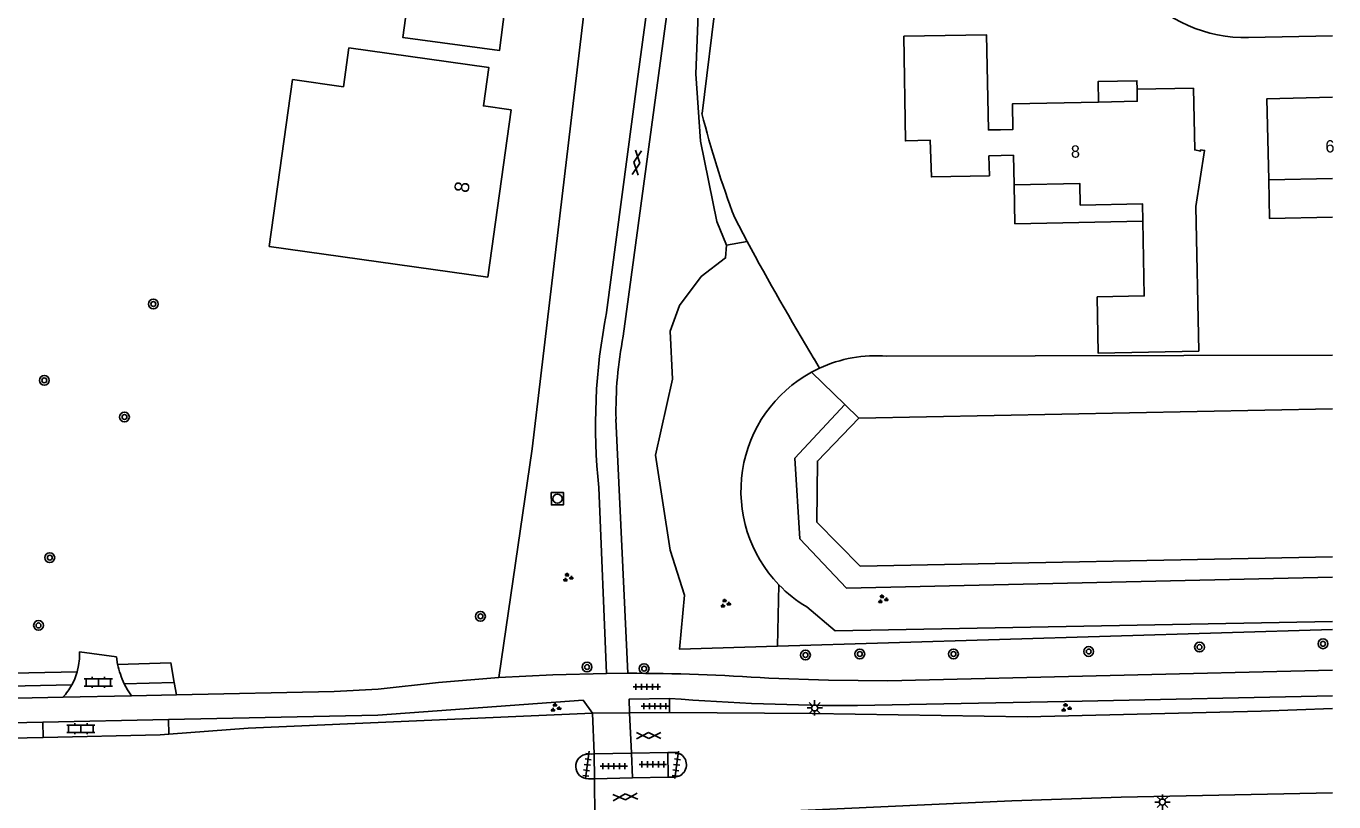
# Model space of a CAD drawing. Extents: x 128999 to 131010, y 395498 to 399007.
# Drawn here: x 130893.3 to 131000.1, y 396136.1 to 396199.4 of the extents above; entities that cross this region are included whole.
import ezdxf

# ---------------------------------------------------------------- set-up
doc = ezdxf.new("R2010")
doc.units = 0
for name, color, linetype in [('gg-afsc-erfafscheiding', 7, 'Continuous'), ('gg-afsc-hekwerk', 7, 'Continuous'), ('gg-anno-huisnummerreeks BGT', 7, 'Continuous'), ('gg-bbg-hoofdgebouw', 7, 'Continuous'), ('gg-bbg-luifel en loopbrug', 7, 'Continuous'), ('gg-bbg-overig bouwwerk', 7, 'Continuous'), ('gg-knt-BGT kruinlijn', 7, 'Continuous'), ('gg-knt-verharding', 7, 'Continuous'), ('gg-knt-verharding nz', 7, 'Continuous'), ('gg-kntw-beschoeiing', 7, 'Continuous'), ('gt-anno-plantopografie huisnummer', 7, 'Continuous'), ('gt-bbg-plantopografie pand', 7, 'Continuous'), ('gt-grn-groengrens', 7, 'Continuous'), ('gt-grn-groengrens NZ', 7, 'Continuous'), ('gt-grn-vlakafsluiter', 7, 'Continuous'), ('gt-grn-weggrens', 7, 'Continuous'), ('gt-symb-boom', 7, 'Continuous'), ('gt-symb-gesloten verharding', 7, 'Continuous'), ('gt-symb-groenvak', 7, 'Continuous'), ('gt-symb-klinker verharding', 7, 'Continuous'), ('gt-symb-lichtmast', 7, 'Continuous'), ('gt-symb-rioolschacht', 7, 'Continuous'), ('gt-symb-tegel verharding', 7, 'Continuous')]:
    doc.layers.add(name, color=color, linetype=linetype)

# ---------------------------------------------------------------- blocks, each defined once
blk = doc.blocks.new('gt0-GRVAK')
at = {"layer": 'gt-symb-groenvak'}
for p, q in [((-0.11, 0.19), (-0.23, 0.24)), ((-0.18, 0.15), (0.09, 0.15)), ((-0.09, 0.21), (-0.16, 0.32)), ((-0.05, 0.21), (-0.05, 0.39)), ((0, 0.21), (0.06, 0.32)), ((0.01, 0.19), (0.13, 0.24)), ((0.26, -0.05), (0.2, 0.06)), ((0.31, -0.05), (0.31, 0.13)), ((0.35, -0.05), (0.41, 0.06)), ((-0.24, -0.23), (-0.36, -0.18)), ((-0.32, -0.26), (-0.05, -0.26)), ((-0.23, -0.21), (-0.29, -0.1)), ((-0.18, -0.2), (-0.18, -0.02)), ((-0.14, -0.21), (-0.07, -0.1)), ((-0.12, -0.23), (0, -0.18)), ((0.24, -0.07), (0.12, -0.02)), ((0.17, -0.11), (0.44, -0.11)), ((0.37, -0.07), (0.49, -0.02))]:
    blk.add_line(p, q, dxfattribs=at)
blk = doc.blocks.new('gt0-BOOM')
at = {"layer": 'gt-symb-boom'}
for radius in [0.4, 0.2]:
    blk.add_circle((0, 0), radius, dxfattribs=at)
blk = doc.blocks.new('gt0-LMAST')
at = {"layer": 'gt-symb-lichtmast'}
for p, q in [((-0.18, 0.17), (-0.45, 0.44)), ((-0.01, 0.25), (-0.01, 0.62)), ((0.17, 0.17), (0.44, 0.44)), ((-0.26, 0), (-0.63, 0)), ((-0.18, -0.18), (-0.45, -0.45)), ((-0.01, -0.25), (-0.01, -0.63)), ((0.44, -0.45), (0.17, -0.18)), ((0.24, 0), (0.62, 0))]:
    blk.add_line(p, q, dxfattribs=at)
blk.add_circle((-0.01, 0), 0.25, dxfattribs=at)
blk = doc.blocks.new('gt0-GESVH1')
at = {"layer": 'gt-symb-gesloten verharding'}
for p, q in [((-0.99, -0.26), (0.01, 0.24)), ((0.01, -0.26), (-0.99, 0.24)), ((0.01, 0.24), (1.01, -0.26)), ((1.01, 0.24), (0.01, -0.26))]:
    blk.add_line(p, q, dxfattribs=at)
blk = doc.blocks.new('gt0-TEG1')
at = {"layer": 'gt-symb-tegel verharding'}
for p, q in [((-1.12, 0), (1.12, 0)), ((-0.9, -0.25), (-0.9, 0.25)), ((-0.45, -0.25), (-0.45, 0.25)), ((0, -0.25), (0, 0.25)), ((0.45, -0.25), (0.45, 0.25)), ((0.9, -0.25), (0.9, 0.25))]:
    blk.add_line(p, q, dxfattribs=at)
blk = doc.blocks.new('gt0-RS')
at = {"layer": 'gt-symb-rioolschacht'}
blk.add_lwpolyline([(-0.5, -0.5), (0.5, -0.5), (0.5, 0.5), (-0.5, 0.5)], close=True, dxfattribs=at)
blk.add_circle((0, 0), 0.375, dxfattribs=at)
blk = doc.blocks.new('gt0-KL1')
at = {"layer": 'gt-symb-klinker verharding'}
for p, q in [((-1.15, 0.3), (1.15, 0.3)), ((-1, -0.3), (-1, 0.3)), ((-0.5, 0.3), (-0.5, 0.45)), ((0, -0.3), (0, 0.3)), ((0.5, 0.3), (0.5, 0.45)), ((1, -0.3), (1, 0.3)), ((-1.15, -0.3), (1.15, -0.3)), ((-0.5, -0.45), (-0.5, -0.3)), ((0.5, -0.45), (0.5, -0.3))]:
    blk.add_line(p, q, dxfattribs=at)

msp = doc.modelspace()

# ---------------------------------------------------------------- linework, layer by layer
at = {"layer": 'gg-afsc-erfafscheiding'}
for p, q in [((130949.74, 396202.34), (130948.49, 396192.28)), ((130951.17, 396183.76), (130952.18, 396181.84))]:
    msp.add_line(p, q, dxfattribs=at)
for centre, radius, start, end in [((131020.59, 396210.25), 74.31, 193.9939, 200.8834), ((131131.92, 396277.93), 203.81, 208.1296, 211.238)]:
    msp.add_arc(centre, radius, start, end, dxfattribs=at)
at = {"layer": 'gg-afsc-hekwerk'}
msp.add_line((130893.5, 396146.63), (130786.07, 396144.29), dxfattribs=at)
at = {"layer": 'gg-bbg-hoofdgebouw'}
msp.add_line((130994.79, 396186.87), (131000, 396186.98), dxfattribs=at)
for points in [[(130980.88, 396193.21), (130973.84, 396193.06), (130973.89, 396190.97), (130972.88, 396190.95), (130971.88, 396190.93), (130971.73, 396198.69), (130964.98, 396198.58), (130965.11, 396190.03), (130967.12, 396190.1), (130967.23, 396187.1), (130971.97, 396187.19), (130971.93, 396188.81), (130973.93, 396188.86), (130973.98, 396186.46)], [(130984.5, 396183.49), (130984.62, 396177.39), (130980.77, 396177.31), (130980.86, 396172.71), (130989.07, 396172.88), (130988.83, 396184.67), (130989.54, 396189.26), (130989.22, 396189.3), (130989.21, 396189.21), (130988.74, 396189.3), (130988.63, 396194.34), (130984.03, 396194.26)], [(130984.03, 396194.26), (130984.04, 396193.27), (130980.88, 396193.21)], [(130994.79, 396186.87), (130994.64, 396193.48), (131000, 396193.6)], [(130973.98, 396186.46), (130979.35, 396186.57), (130979.39, 396184.8), (130984.47, 396184.91), (130984.5, 396183.49)]]:
    msp.add_lwpolyline(points, dxfattribs=at)
at = {"layer": 'gg-bbg-luifel en loopbrug'}
for points in [[(130984.03, 396194.26), (130984.01, 396194.95), (130980.85, 396194.88), (130980.88, 396193.21)], [(130973.98, 396186.46), (130974.05, 396183.27), (130984.5, 396183.49)], [(130994.79, 396186.87), (130994.85, 396183.7), (131000, 396183.81)]]:
    msp.add_lwpolyline(points, dxfattribs=at)
at = {"layer": 'gg-bbg-overig bouwwerk'}
msp.add_lwpolyline([(130924.52, 396201.86), (130932.37, 396200.82), (130931.95, 396197.42), (130924.04, 396198.49), (130924.52, 396201.86)], dxfattribs=at)
at = {"layer": 'gg-knt-BGT kruinlijn'}
for p, q in [((130963.57, 396172.46), (131000, 396172.54)), ((130958.08, 396171.48), (130957.43, 396171.16))]:
    msp.add_line(p, q, dxfattribs=at)
msp.add_lwpolyline([(130957.04, 396152), (130959.37, 396150.04), (131000, 396150.82)], dxfattribs=at)
for centre, radius, start, end in [((130962.69, 396161.48), 11.02, 85.4047, 114.7196), ((130962.69, 396161.47), 11.02, 118.4832, 224.0429), ((130962.71, 396161.49), 11.05, 224.0778, 239.1459)]:
    msp.add_arc(centre, radius, start, end, dxfattribs=at)
at = {"layer": 'gg-knt-verharding'}
for p, q in [((130942.05, 396174.1), (130953, 396254.85)), ((130993.14, 396198.47), (131000, 396198.61)), ((130942.43, 396146.58), (130941.46, 396167.33)), ((130940.7, 396146.57), (130940.06, 396161.74)), ((130897.56, 396147.21), (130897.44, 396146.71)), ((130940.7, 396146.57), (130942.43, 396146.58)), ((130896.29, 396144.63), (130901.89, 396144.75)), ((130901.89, 396144.75), (130905.55, 396144.82)), ((130945.83, 396144.53), (130945.82, 396143.39)), ((130904.9, 396142.8), (130894.64, 396142.58)), ((130894.68, 396141.35), (130894.64, 396142.58)), ((130904.9, 396142.8), (130904.94, 396141.6)), ((130942.57, 396143.36), (130939.53, 396143.33)), ((130945.82, 396143.39), (130942.57, 396143.36)), ((130894.68, 396141.35), (130904.23, 396141.55)), ((130904.23, 396141.55), (130904.94, 396141.6)), ((130939.14, 396139.99), (130939.67, 396140)), ((130942.72, 396140.07), (130939.67, 396140)), ((130939.72, 396137.97), (130939.67, 396140)), ((130945.7, 396140.13), (130942.72, 396140.07)), ((130946.16, 396140.13), (130945.7, 396140.13)), ((130945.7, 396140.13), (130945.73, 396138.1)), ((130945.73, 396138.1), (130942.8, 396138.04)), ((130945.73, 396138.1), (130946.22, 396138.11)), ((130939.72, 396137.97), (130939.21, 396137.97)), ((130942.8, 396138.04), (130939.72, 396137.97))]:
    msp.add_line(p, q, dxfattribs=at)
for points in [[(130940.68, 396176.02), (130943.19, 396194.9), (130951.28, 396254.54), (130955.32, 396284.06)], [(130900.74, 396147.31), (130900.65, 396147.92), (130897.64, 396148.32), (130897.63, 396147.76), (130897.56, 396147.21)], [(130897.44, 396146.71), (130897.44, 396146.7), (130897.27, 396146.2)], [(130953.95, 396146.19), (130958.81, 396146.02), (130963.68, 396145.98), (131000, 396146.84)], [(130901.89, 396144.75), (130901.57, 396145.22), (130901.29, 396145.73)], [(130905.55, 396144.82), (130918.43, 396145.1), (130922.04, 396145.29), (130926.96, 396145.84), (130931.9, 396146.23)], [(130940.7, 396146.57), (130936.29, 396146.46), (130931.9, 396146.23)], [(130896.29, 396144.63), (130837.07, 396143.36), (130785.95, 396142.22)], [(130961.18, 396143.95), (130979.55, 396144.31), (131000, 396144.73)], [(130904.9, 396142.8), (130922.01, 396143.16), (130938.78, 396144.38), (130939.53, 396143.33)], [(130945.82, 396143.39), (130957.49, 396143.29), (130975.05, 396143.04), (130994.16, 396143.48), (131000, 396143.7)], [(130894.64, 396142.58), (130837.21, 396141.39), (130785.06, 396140.2)], [(130939.53, 396143.33), (130911.41, 396142.09), (130904.94, 396141.6)], [(130786.36, 396138.98), (130837.3, 396140.15), (130894.68, 396141.35)], [(130944.44, 396134.86), (130945.86, 396134.9), (130973.8, 396136.18), (130982.72, 396136.46), (131000, 396136.82)]]:
    msp.add_lwpolyline(points, dxfattribs=at)
for centre, radius, start, end in [((130992.9, 396210.22), 11.75, 172.1004, 271.1646), ((130987.3, 396166.82), 47.51, 168.8391, 186.1403), ((130972.68, 396168.03), 31.22, 168.7983, 181.2849), ((130907.25, 396148.67), 6.64, 191.7899, 206.2501), ((130892.45, 396148.12), 5.19, 317.6606, 331.467), ((130892.53, 396148.09), 5.11, 331.3872, 338.3095), ((130942.59, 395983.2), 163.38, 86.0147, 90.0553), ((130960.78, 396336.71), 192.76, 265.5525, 270.1203), ((130939.18, 396138.98), 1.01, 92.423, 271.5641), ((130946.21, 396139.12), 1.01, 270.382, 92.7988)]:
    msp.add_arc(centre, radius, start, end, dxfattribs=at)
at = {"layer": 'gg-knt-verharding nz'}
msp.add_line((130942.72, 396140.07), (130942.8, 396138.04), dxfattribs=at)
msp.add_lwpolyline([(130945.83, 396144.53), (130942.53, 396144.46), (130942.57, 396143.36)], dxfattribs=at)
at = {"layer": 'gg-kntw-beschoeiing'}
msp.add_line((130961.31, 396167.41), (131000, 396168.17), dxfattribs=at)
msp.add_lwpolyline([(130961.31, 396167.41), (130957.91, 396163.9), (130957.88, 396158.92), (130961.42, 396155.32), (131000, 396156.09)], dxfattribs=at)
at = {"layer": 'gt-bbg-plantopografie pand'}
msp.add_lwpolyline([(130913.14, 396181.42), (130930.98, 396178.92), (130932.89, 396192.57), (130930.63, 396192.89), (130931.07, 396196.03), (130919.65, 396197.63), (130919.2, 396194.46), (130915.05, 396195.04), (130913.14, 396181.42)], dxfattribs=at)
at = {"layer": 'gt-grn-groengrens'}
for p, q in [((130952.18, 396181.84), (130950.48, 396181.54)), ((130957.43, 396171.16), (130960.15, 396168.52)), ((130960.15, 396168.52), (130961.31, 396167.41)), ((130934.61, 396164.89), (130931.9, 396146.23)), ((130954.66, 396148.79), (130954.76, 396153.8)), ((130954.66, 396148.79), (131000, 396150.17)), ((130905.38, 396145.82), (130905.55, 396144.82))]:
    msp.add_line(p, q, dxfattribs=at)
for points in [[(130955.36, 396254.63), (130948.25, 396202.54), (130947.98, 396195.5), (130948.37, 396190.01), (130949.7, 396183.46), (130950.48, 396181.54)], [(130950.48, 396181.54), (130950.42, 396180.49), (130948.42, 396178.96), (130946.64, 396176.61), (130945.88, 396174.51), (130946.07, 396170.59), (130944.69, 396164.38), (130945.88, 396156.63), (130947.07, 396152.97), (130946.66, 396148.55), (130954.66, 396148.79)], [(130960.15, 396168.52), (130956.06, 396164.14), (130956.49, 396157.57), (130960.3, 396153.54), (131000, 396154.42)], [(130900.74, 396147.31), (130905.11, 396147.43), (130905.38, 396145.82)]]:
    msp.add_lwpolyline(points, dxfattribs=at)
at = {"layer": 'gt-grn-groengrens NZ'}
msp.add_line((130901.29, 396145.73), (130905.38, 396145.82), dxfattribs=at)
msp.add_lwpolyline([(130897.01, 396145.64), (130837.05, 396144.36), (130785.08, 396143.2)], dxfattribs=at)
at = {"layer": 'gt-grn-vlakafsluiter'}
for p, q in [((130948.91, 396285.41), (130934.61, 396164.89)), ((130958.08, 396171.48), (130957.66, 396172.24)), ((130893.5, 396146.63), (130897.44, 396146.71))]:
    msp.add_line(p, q, dxfattribs=at)
at = {"layer": 'gt-grn-weggrens'}
for p, q in [((130939.67, 396140), (130939.53, 396143.33)), ((130942.57, 396143.36), (130942.72, 396140.07)), ((130939.73, 396134.75), (130939.72, 396137.97))]:
    msp.add_line(p, q, dxfattribs=at)

# ---------------------------------------------------------------- block references
at = {"layer": 'gt-symb-boom'}
for p, rotation in [((130903.67, 396176.72), 6.662963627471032), ((130894.76, 396170.49), 6.662963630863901), ((130901.31, 396167.5), 6.662963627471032), ((130895.21, 396156.02), 6.662963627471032), ((130894.29, 396150.49), 6.662963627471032)]:
    msp.add_blockref('gt0-BOOM', p, dxfattribs=dict(at, rotation=rotation))
for p in [(130930.39, 396151.23), (130989.13, 396148.72), (130999.22, 396148.99), (130956.94, 396148.07), (130961.38, 396148.16), (130969.03, 396148.16), (130980.08, 396148.36), (130939.1, 396147.09), (130943.76, 396146.96)]:
    msp.add_blockref('gt0-BOOM', p, dxfattribs=at)
at = {"layer": 'gt-symb-gesloten verharding'}
for p, rotation in [((130943.17, 396188.27), -98.04906170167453), ((130944.14, 396141.49), -179.42706130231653), ((130942.21, 396136.5), 3.554888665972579)]:
    msp.add_blockref('gt0-GESVH1', p, dxfattribs=dict(at, rotation=rotation))
at = {"layer": 'gt-symb-groenvak'}
for p in [(130937.51, 396154.4), (130950.38, 396152.28), (130963.24, 396152.63)]:
    msp.add_blockref('gt0-GRVAK', p, dxfattribs=at)
for p, rotation in [((130936.51, 396143.76), -2.979673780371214), ((130978.22, 396143.76), -2.9796737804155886)]:
    msp.add_blockref('gt0-GRVAK', p, dxfattribs=dict(at, rotation=rotation))
at = {"layer": 'gt-symb-klinker verharding'}
for p in [(130899.18, 396145.84), (130897.75, 396142.05)]:
    msp.add_blockref('gt0-KL1', p, dxfattribs=at)
at = {"layer": 'gt-symb-lichtmast'}
for p in [(130957.7, 396143.76), (130986.11, 396136.07)]:
    msp.add_blockref('gt0-LMAST', p, dxfattribs=at)
at = {"layer": 'gt-symb-rioolschacht', "rotation": -89.65622944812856}
msp.add_blockref('gt0-RS', (130936.68, 396160.83), dxfattribs=at)
at = {"layer": 'gt-symb-tegel verharding'}
for p, rotation in [((130943.99, 396145.48), -179.82811317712), ((130939.12, 396139.11), -97.64386978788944), ((130946.42, 396139.11), -97.64386978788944), ((130941.29, 396139), 0.11459140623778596)]:
    msp.add_blockref('gt0-TEG1', p, dxfattribs=dict(at, rotation=rotation))
for p in [(130944.64, 396143.9), (130944.48, 396139.15)]:
    msp.add_blockref('gt0-TEG1', p, dxfattribs=at)

# ---------------------------------------------------------------- texts
at = {"layer": 'gg-anno-huisnummerreeks BGT'}
for s, rotation, p in [('8', 1.2, (130978.63, 396188.66)), ('6', 1.3, (130999.42, 396189.09))]:
    msp.add_text(s, height=1, rotation=rotation, dxfattribs=at).set_placement(p)
at = {"layer": 'gt-anno-plantopografie huisnummer'}
msp.add_text('8', height=1.2, rotation=82.0171, dxfattribs=at).set_placement((130929.41, 396185.75))

doc.saveas('drawing.dxf')
